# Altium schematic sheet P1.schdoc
size 297 x 209 mm; Symbol: Drawing-Symbol_A4; Company: 嘉立创EDA; Version: V1.0; Page Size: A4; @Project Name: liuxin の 项目; @Page Count: 1; @Update Date: 2025-09-11; @Create Date: 2025-09-11; @Schematic Name: Schematic1; @Page No: 1; @Page Name: P1; @Create Time: 13:08:40; @Update Time: 18:29:36; Border: 1; Width: 1170; Height: 825; Region Start: 1; X Region Count: 6; Y Region Count: 4; Blade Width: 10; Title Block Position: 3; @Board Name: Board1; Device: Drawing-Symbol_A4
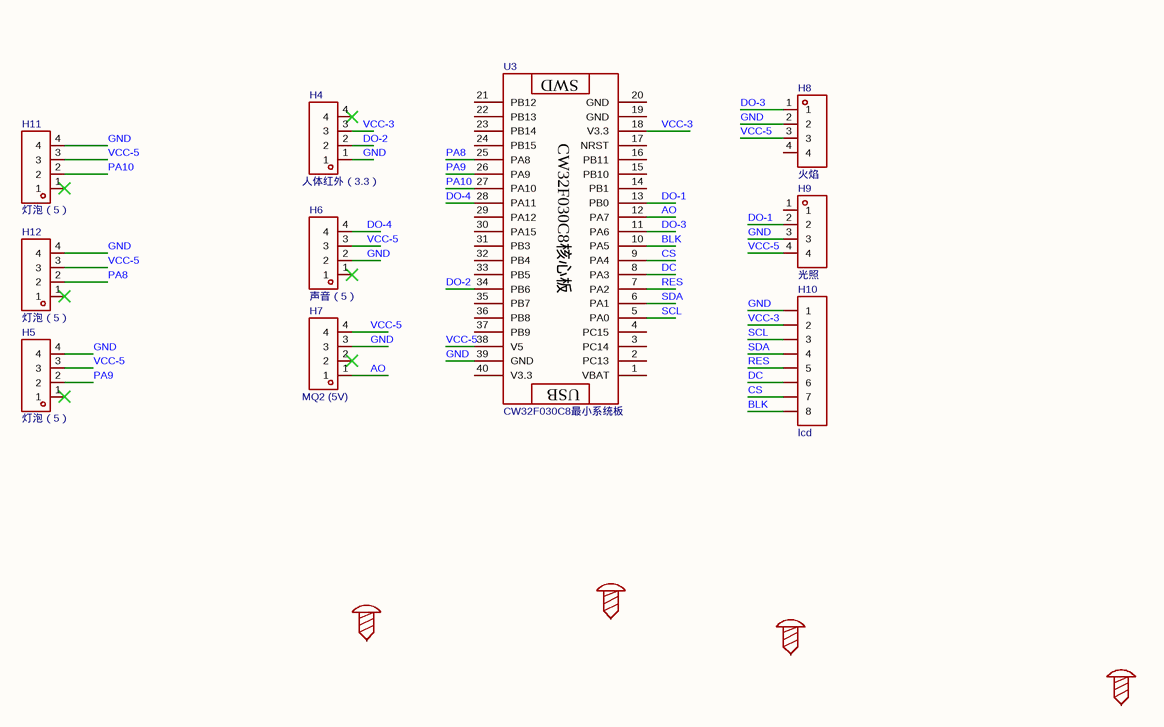
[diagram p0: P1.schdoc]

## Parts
H4  人体红外（3.3）  [HDR-TH_4P-P2.54-V-F]
H5  灯泡（5）  [HDR-TH_4P-P2.54-V-F]
H6  声音（5）  [HDR-TH_4P-P2.54-V-F]
H7  MQ2 (5V)  [HDR-TH_4P-P2.54-V-F]
H8  火焰  [HDR-TH_4P-P2.54-V-F]
H9  光照  [HDR-TH_4P-P2.54-V-F]
H10  lcd  [HDR-TH_8P-P2.54-V-F-1]
H11  灯泡（5）  [HDR-TH_4P-P2.54-V-F]
H12  灯泡（5）  [HDR-TH_4P-P2.54-V-F]
SCREW1  (no value)  [M2螺丝]
SCREW2  (no value)  [M2螺丝]
SCREW3  (no value)  [M2螺丝]
SCREW4  (no value)  [M2螺丝]
U3  CW32F030C8最小系统板  [STM32F103C8T6核心板]

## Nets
AO: H7.1 U3.12(PA7)
BLK: H10.8 U3.10(PA5)
CS: H10.7 U3.9(PA4)
DC: H10.6 U3.8(PA3)
DO-1: H9.2 U3.13(PB0)
DO-2: H4.2 U3.34(PB6)
DO-3: H8.1 U3.11(PA6)
DO-4: H6.4 U3.28(PA11)
GND: H4.1 H5.4 H6.2 H7.3 H8.2 H9.3 H10.1 H11.4 H12.4 U3.39(GND)
PA8: H12.2 U3.25(PA8)
PA9: H5.2 U3.26(PA9)
PA10: H11.2 U3.27(PA10)
RES: H10.5 U3.7(PA2)
SCL: H10.3 U3.5(PA0)
SDA: H10.4 U3.6(PA1)
VCC-3: H4.3 H10.2 U3.18(V3.3)
VCC-5: H5.3 H6.3 H7.4 H8.3 H9.4 H11.3 H12.3 U3.38(V5)

Not connected (* = marked no-connect by the designer): H4 4*; H5 1*; H6 1*; H7 2*; H8 4; H9 1; H11 1*; H12 1*; SCREW1 1; SCREW2 1; SCREW3 1; SCREW4 1; U3 1(VBAT) 2(PC13) 3(PC14) 4(PC15) 14(PB1) 15(PB10) 16(PB11) 17(NRST) 19(GND) 20(GND) 21(PB12) 22(PB13) 23(PB14) 24(PB15) 29(PA12) 30(PA15) 31(PB3) 32(PB4) 33(PB5) 35(PB7) 36(PB8) 37(PB9) 40(V3.3)

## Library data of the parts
H4-H7 H11 H12 = 2.54-1*4P母: 插孔结构:1x4P;间距:2.54mm;行距:-;圆孔/方孔:方孔;安装方式:直插;排数:单排;总孔位数:4P;额定电流:3A;额定电压:-;插孔方向:顶部;塑高:-;触头材质:青铜;触头镀层:-;工作温度:-40℃~+105℃;; Manufacturer: BOOMELE(博穆精密); AddInBom: yes; ModelId: d187812051054f85879fcaa51a310d8e; ModelTransform: 419.6842,98.464,0,0,0,0,0,0,-118.11; Holes Structure: 1x4P; Pitch: 2.54mm; Circular Hole / Square Hole: 方孔; Number of Positions: 4P; Current Rating: 3A; Holes Direction: 顶部
H8 H9 = HDR-F_2.54_1x4P: Symbol: 2.54-1*4P母; ConvertToPcb: yes; ModelId: d187812051054f85879fcaa51a310d8e; ModelTransform: 419.6842,98.464,0,0,0,0,0,0,-118.11
H10 = HDR-F_2.54_1x8P: Symbol: Header-Female-2.54_1x8; AddInBom: yes; ModelId: 0f7e4d9227ef4fa08d5469c22cc70cdb; ModelName: HDR-F-2.54_1x8; ModelTransform: 799.99844,100,0,0,0,0,0,0,-118.11
SCREW1-SCREW4 = M2螺丝: ConvertToPcb: yes; SymbolName: 螺丝孔
U3 = STM32F103C8T6最小系统板: Manufacturer: 无; ManufacturerPart: STM32F103C8T6最小系统模块; AddInBom: yes; tags: STM32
